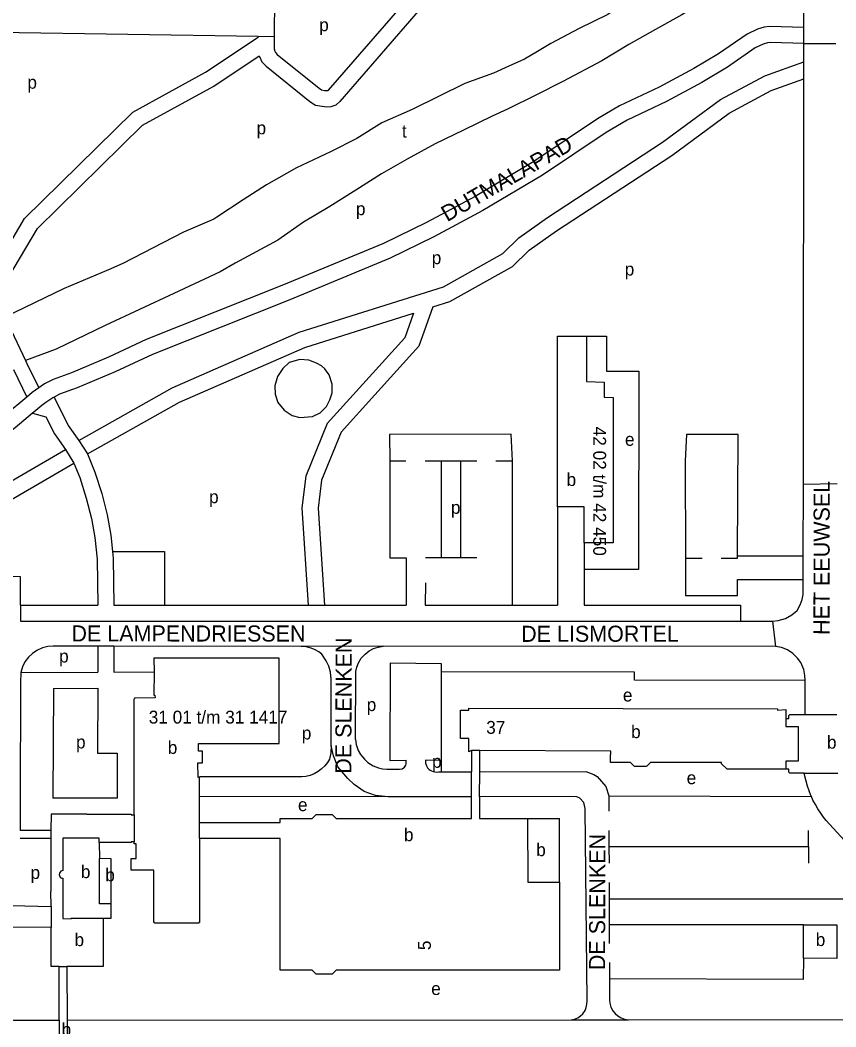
# Model space of a CAD drawing. Extents: x 161494 to 163033, y 383688 to 384862.
# Drawn here: x 161937.8 to 162191.5, y 384379.7 to 384692.8 of the extents above; entities that cross this region are included whole.
import ezdxf

# ---------------------------------------------------------------- set-up
doc = ezdxf.new("R2010")
doc.units = 0
for name, color, linetype in [('BLT_Basislijn', 7, 'Continuous'), ('BLT_Bebouwing', 7, 'Continuous'), ('BLT_Centroide', 7, 'Continuous'), ('BLT_Huisnummer', 7, 'Continuous'), ('BLT_Huisnummer_reeks', 7, 'Continuous'), ('BLT_Onderdoorgang_en_onderverdeling', 7, 'Continuous'), ('BLT_Onderverdeling_panden', 7, 'Continuous'), ('BLT_Straatnaam', 7, 'Continuous'), ('BLT_Vlakafsluiter', 7, 'Continuous')]:
    doc.layers.add(name, color=color, linetype=linetype)

msp = doc.modelspace()

# ---------------------------------------------------------------- linework, layer by layer
at = {"layer": 'BLT_Basislijn'}
for p, q in [((162016.89, 384703.11), (162016.86, 384687.59)), ((162181.54, 384685.47), (162181.58, 384690.47)), ((162011.86, 384687.67), (161924.77, 384689)), ((162016.86, 384687.59), (162011.86, 384687.67)), ((162011.86, 384687.67), (162011.86, 384687.48)), ((162181.54, 384679.83), (162181.54, 384685.47)), ((162181.53, 384674.52), (162181.54, 384679.83)), ((161933.32, 384599.9), (161939.51, 384586.93)), ((161939.51, 384586.93), (161939.95, 384586.02)), ((161935.8, 384584.12), (161939.88, 384575.55)), ((161939.95, 384586.02), (161943.64, 384578.39)), ((161939.6, 384576.15), (161939.92, 384575.48)), ((161956.03, 384562.03), (161958.78, 384557.84)), ((162160.93, 384526.09), (162161.16, 384563.86)), ((161951.91, 384559.21), (161954.55, 384554.96)), ((162052.76, 384555.73), (162057.83, 384555.71)), ((162063.83, 384555.71), (162068.84, 384555.71)), ((162068.84, 384555.71), (162074.81, 384555.73)), ((162068.88, 384525.52), (162068.84, 384555.71)), ((162074.81, 384555.73), (162079.83, 384555.73)), ((162074.81, 384555.73), (162074.82, 384525.52)), ((162085.82, 384555.72), (162090.97, 384555.72)), ((162104.97, 384541.44), (162104.95, 384510.84)), ((162113.27, 384530.18), (162113.26, 384521.96)), ((162068.88, 384525.52), (162063.88, 384525.55)), ((162074.82, 384525.52), (162068.88, 384525.52)), ((162079.83, 384525.51), (162074.82, 384525.52)), ((162144.72, 384525.48), (162149.9, 384525.49)), ((162113.26, 384521.96), (162113.25, 384510.84)), ((161982.68, 384510.82), (162027.43, 384510.83)), ((162027.43, 384510.83), (162032.44, 384510.83)), ((162032.44, 384510.83), (162057.84, 384510.83)), ((161938.06, 384489.92), (161961.94, 384490)), ((161966.94, 384490.02), (161979.47, 384490.06)), ((162068.9, 384462.53), (162068.89, 384490.05)), ((161948.15, 384484.96), (161948, 384450.8)), ((161948.15, 384484.96), (161961.96, 384485)), ((162052.25, 384451.18), (161993.63, 384451.3)), ((162120.9, 384451.58), (162120.92, 384446.72)), ((162188.54, 384443.92), (162202.39, 384428.59)), ((162120.94, 384440.71), (162120.96, 384435.72)), ((162183.02, 384435.72), (162183.02, 384440.72)), ((162183.02, 384435.72), (162120.96, 384435.72)), ((162120.96, 384435.72), (162120.98, 384430.56)), ((162183.02, 384435.72), (162183.02, 384430.57)), ((162121, 384424.58), (162121.02, 384419.5)), ((162121.02, 384419.5), (162121.05, 384411.45)), ((162181.45, 384411.45), (162121.05, 384411.45)), ((162121.05, 384411.45), (162121.07, 384405.65)), ((162121.09, 384399.74), (162121.11, 384394.62)), ((161952.4, 384381.82), (162109.2, 384381.87)), ((162127.04, 384381.9), (162197.47, 384381.94))]:
    msp.add_line(p, q, dxfattribs=at)
for points in [[(162129.11, 384719.89), (162129.02, 384714.31), (162102.45, 384714.98), (162102.34, 384709.99), (162074.52, 384710.46), (162037.26, 384667.41)], [(162148.13, 384713.48), (162144.15, 384710.95), (162136.26, 384705.43), (162127.66, 384699.69), (162120.65, 384694.55), (162111.65, 384690.15), (162102.89, 384685.49)], [(162181.58, 384690.47), (162181.57, 384697.92), (162179.73, 384698.26), (162179.65, 384698.65), (162179.7, 384710.65)], [(162033.72, 384670.96), (162060.84, 384702.3), (162016.89, 384703.11)], [(162152.23, 384699.94), (162143.61, 384694.45), (162135.39, 384689.81), (162127.17, 384685.16), (162118.75, 384680.11), (162106.58, 384673.66)], [(162181.58, 384690.47), (162170.99, 384690.82), (162169.27, 384690.61), (162167.13, 384689.99), (162163.92, 384688.44), (162155.07, 384682.28), (162147.39, 384677.7), (162136.59, 384671.9), (162124.27, 384666.11), (162117.38, 384662.05), (162097.62, 384648.8), (162079.31, 384637.89), (162064.26, 384629.82), (162050.86, 384623.33), (162019.78, 384610.42), (161977.05, 384593.41), (161965.31, 384587.97), (161953.76, 384583.06), (161948.07, 384581), (161945.42, 384579.62), (161943.64, 384578.39)], [(161927.72, 384611.79), (161939.21, 384631.09), (161972.91, 384664.14), (161995.43, 384676.54), (162011.86, 384687.48)], [(162016.86, 384687.59), (162016.85, 384683.82), (162017.01, 384683.09), (162017.21, 384682.66), (162017.76, 384682.08), (162030.81, 384671.55), (162031.56, 384671.1), (162032.46, 384670.92), (162033.26, 384670.84), (162033.61, 384670.86), (162033.72, 384670.96)], [(162181.54, 384685.47), (162171.21, 384685.81), (162170.27, 384685.7), (162168.93, 384685.31), (162166.45, 384684.11), (162157.78, 384678.08), (162149.86, 384673.35), (162138.84, 384667.43), (162126.61, 384661.68), (162120.04, 384657.82), (162100.29, 384644.57), (162081.78, 384633.54), (162066.53, 384625.37), (162052.91, 384618.77), (162021.66, 384605.79), (161979.03, 384588.82), (161967.34, 384583.4), (161955.59, 384578.41), (161950.09, 384576.41), (161948.36, 384575.51)], [(162102.89, 384685.49), (162098.77, 384683.04), (162094.64, 384680.59), (162089.84, 384678.41), (162085.04, 384676.24), (162076.12, 384673.08), (162067.93, 384669.03), (162059.75, 384664.98)], [(161930.29, 384606.33), (161943.18, 384627.98), (161975.92, 384660.1), (161998.03, 384672.26), (162012.19, 384681.69)], [(162012.19, 384681.69), (162012.24, 384681.48), (162013.04, 384679.79), (162014.37, 384678.39), (162027.93, 384667.44), (162029.72, 384666.36), (162031.72, 384665.97), (162033.18, 384665.82), (162034.57, 384665.92), (162036.07, 384666.38), (162037.26, 384667.41)], [(161956.03, 384562.03), (161985.15, 384578.44), (162024.57, 384595.69), (162069.49, 384609.84), (162087.97, 384620.17), (162092.95, 384625.08), (162101.81, 384631.37), (162137.64, 384654.77), (162155.64, 384668.09), (162169.39, 384675.47), (162181.54, 384679.83)], [(162066.16, 384603.55), (162071.48, 384605.23), (162091, 384616.13), (162096.17, 384621.23), (162104.62, 384627.24), (162140.5, 384650.66), (162158.32, 384663.86), (162171.43, 384670.89), (162181.53, 384674.52)], [(162181.47, 384548.49), (162181.48, 384572.05), (162181.53, 384674.52)], [(162106.58, 384673.66), (162098.22, 384669.44), (162089.36, 384665.08), (162084.61, 384662.86), (162075.75, 384658.55), (162066.89, 384654.24), (162058.17, 384649.52)], [(162059.75, 384664.98), (162050.36, 384660.84), (162042.49, 384655.98), (162034.34, 384651.83), (162029.05, 384649.32), (162023.76, 384646.81), (162014.45, 384641.59), (162007.23, 384636.84)], [(162058.17, 384649.52), (162050.23, 384645.01), (162042.18, 384639.9), (162034.12, 384634.79), (162025.97, 384629.93), (162018, 384624.3), (162004.71, 384617.15)], [(162007.23, 384636.84), (161999.01, 384631.46), (161998.02, 384630.82), (161988.6, 384626.81), (161979.17, 384621.93), (161969.73, 384617.06), (161965.3, 384615.12)], [(161965.3, 384615.12), (161951.55, 384609.34), (161933.1, 384600.35)], [(162004.71, 384617.15), (162000, 384614.53), (161985.64, 384607.72), (161964.3, 384597.76)], [(162066.16, 384603.55), (162061.86, 384591.4), (162048.17, 384576.26), (162037.66, 384564.63), (162031.57, 384549.65), (162030.5, 384541), (162032.44, 384510.83)], [(161958.78, 384557.84), (161987.38, 384573.96), (162026.33, 384591), (162060.19, 384601.67)], [(162060.19, 384601.67), (162057.48, 384594.01), (162033.36, 384567.33), (162026.69, 384550.92), (162025.48, 384541.14), (162027.43, 384510.83)], [(161964.3, 384597.76), (161949.05, 384590.48), (161939.51, 384586.93)], [(162113.93, 384594.52), (162120.16, 384594.52), (162120.15, 384583.57), (162130.26, 384583.56), (162130.17, 384521.94), (162113.26, 384521.96)], [(161943.64, 384578.39), (161941.54, 384576.94), (161939.88, 384575.55)], [(161939.88, 384575.55), (161933.16, 384569.9), (161930.17, 384567.61), (161923.57, 384564.05), (161880.13, 384543.25), (161875.48, 384541.33), (161869.42, 384539.18), (161866.4, 384538.3), (161863.11, 384537.18), (161860.29, 384535.54), (161858.06, 384533.63), (161845.78, 384521.31), (161828.11, 384504.08), (161797.59, 384474.82), (161795.64, 384472.79)], [(161948.36, 384575.51), (161948, 384575.33), (161945.83, 384573.83)], [(161948.36, 384575.51), (161952.79, 384566.68), (161956.03, 384562.03)], [(161945.83, 384573.83), (161944.57, 384572.96), (161942.1, 384570.88)], [(161941.64, 384570.5), (161936.29, 384566.01), (161932.9, 384563.4), (161925.84, 384559.59), (161882.17, 384538.68)], [(161942.1, 384570.88), (161941.64, 384570.5)], [(161941.64, 384570.5), (161945.84, 384569.38), (161948.49, 384564.11), (161951.91, 384559.21)], [(162090.97, 384555.72), (162090.5, 384564.04), (162052.74, 384563.94), (162052.76, 384555.73)], [(162161.16, 384563.86), (162145.05, 384563.85), (162144.71, 384555.68)], [(161874.22, 384530.27), (161904.04, 384535.88), (161925.46, 384543.89), (161951.91, 384559.21)], [(161958.78, 384557.84), (161961.04, 384552.24), (161963.2, 384545.51), (161964.9, 384538.87), (161965.98, 384532.58), (161966.52, 384527.52)], [(162052.76, 384555.73), (162052.81, 384525.55), (162057.85, 384525.55), (162057.84, 384510.83)], [(162090.95, 384510.84), (162090.97, 384555.72)], [(162144.71, 384555.68), (162144.72, 384525.48)], [(161866.38, 384519.73), (161875.14, 384525.35), (161905.39, 384531.04), (161927.61, 384539.35), (161954.55, 384554.96)], [(161954.55, 384554.96), (161956.34, 384550.54), (161958.39, 384544.12), (161960, 384537.82), (161961.03, 384531.89), (161961.74, 384525.15), (161961.97, 384510.82)], [(162181.41, 384526.07), (162181.47, 384548.49)], [(161966.52, 384527.52), (161982.68, 384527.52), (161982.68, 384510.82)], [(161966.52, 384527.52), (161966.74, 384525.45), (161966.97, 384510.82)], [(162144.72, 384525.48), (162144.72, 384513.85), (162160.94, 384513.8), (162160.93, 384518.79), (162181.39, 384518.82)], [(162155.89, 384525.45), (162160.92, 384525.46), (162160.93, 384526.09)], [(162181.41, 384526.07), (162160.93, 384526.09)], [(161937.92, 384510.81), (161937.97, 384519.69), (161866.38, 384519.73)], [(162063.85, 384517.79), (162063.82, 384510.83), (162090.95, 384510.84)], [(162171.83, 384505.85), (162173.58, 384506.03), (162175.85, 384506.72), (162177.88, 384507.78), (162179.47, 384509.17), (162180.42, 384510.93), (162181.01, 384512.55), (162181.33, 384514.13), (162181.39, 384515.77), (162181.39, 384518.82)], [(161937.92, 384510.81), (161961.97, 384510.82)], [(161937.92, 384510.81), (161937.92, 384505.81), (162161.9, 384505.85)], [(161966.97, 384510.82), (161982.68, 384510.82)], [(162090.95, 384510.84), (162104.95, 384510.84)], [(162113.25, 384510.84), (162161.9, 384510.85), (162161.9, 384505.85)], [(162161.9, 384505.85), (162171.83, 384505.85)], [(161961.95, 384498.05), (161948.12, 384498.06), (161946.46, 384497.94), (161944.73, 384497.52), (161943.05, 384496.77), (161941.62, 384495.8), (161940.38, 384494.61), (161939.32, 384493.17), (161938.57, 384491.66), (161938.06, 384489.92)], [(161961.95, 384498.05), (161961.94, 384490)], [(161966.95, 384498.04), (161961.95, 384498.05)], [(161966.95, 384498.04), (161966.94, 384490.02)], [(162025.21, 384498), (161966.95, 384498.04)], [(162034.56, 384467.09), (162034.55, 384487.85), (162034.3, 384489.95), (162033.82, 384491.89), (162033.05, 384493.49), (162031.65, 384495.55), (162030.73, 384496.27), (162029.53, 384496.96), (162028.32, 384497.48), (162026.77, 384497.85), (162025.21, 384498)], [(162042.17, 384469.03), (162042.27, 384490.23), (162042.5, 384491.54), (162043.07, 384492.94), (162043.92, 384494.36), (162045.09, 384495.64), (162046.4, 384496.63), (162047.76, 384497.36), (162049.19, 384497.8), (162050.76, 384498.03)], [(162172.71, 384497.96), (162050.76, 384498.03)], [(162181.99, 384487.36), (162181.89, 384489.01), (162181.52, 384490.78), (162180.6, 384492.95), (162179.63, 384494.36), (162178.19, 384495.82), (162176.48, 384496.97), (162174.59, 384497.68), (162172.71, 384497.96)], [(162068.89, 384490.05), (162068.9, 384492.62), (162052.87, 384492.82), (162052.83, 384462.56), (162057.9, 384462.6)], [(161938.06, 384489.92), (161937.9, 384486.8), (161937.83, 384449.68), (161937.82, 384440.72)], [(162181.99, 384487.36), (162128.86, 384487.52), (162128.86, 384490.01), (162068.89, 384490.05)], [(162182.02, 384476.83), (162181.99, 384487.36)], [(161961.96, 384485), (161961.87, 384464.85), (161968.01, 384464.82), (161967.98, 384450.79)], [(162042.17, 384469.03), (162042.33, 384467.49), (162042.99, 384465.59), (162043.72, 384464.37), (162044.94, 384462.97), (162046, 384461.92), (162047.67, 384460.86), (162049.29, 384460.24), (162050.51, 384459.91), (162051.85, 384459.8), (162055.78, 384459.87), (162056.64, 384459.97), (162057.37, 384460.47), (162057.76, 384461.08), (162057.87, 384461.47), (162057.9, 384462.6)], [(162034.56, 384467.09), (162034.46, 384464.89), (162034, 384462.93), (162033.43, 384461.95), (162032.58, 384460.85), (162031.48, 384459.79), (162030.53, 384459.08), (162029.32, 384458.41), (162027.98, 384457.89), (162026.72, 384457.6), (162025.42, 384457.46), (161993.61, 384457.42), (161993.61, 384457.28)], [(162052.25, 384451.18), (162048.39, 384451.62), (162044.81, 384452.92), (162041.71, 384455.07), (162039.77, 384456.89), (162036.66, 384460.51), (162035.27, 384463.98), (162034.56, 384467.09)], [(162068.9, 384462.53), (162063.88, 384462.68), (162063.87, 384462.16), (162063.93, 384461.65), (162064.07, 384461.15), (162064.29, 384460.67), (162064.57, 384460.24), (162064.92, 384459.85), (162065.33, 384459.53), (162065.77, 384459.27), (162066.26, 384459.08), (162066.77, 384458.96), (162067.29, 384458.93), (162067.89, 384458.99), (162068.89, 384458.99)], [(162068.89, 384458.99), (162068.9, 384462.53)], [(162068.89, 384458.99), (162075.36, 384458.99), (162078.23, 384458.99)], [(162080.8, 384459), (162113.74, 384459.1), (162116.28, 384458.22), (162117.33, 384457.52), (162119.94, 384454.41), (162120.9, 384451.58)], [(162183.93, 384451.29), (162183.77, 384451.64), (162183.19, 384453.09), (162182.69, 384454.58), (162182.26, 384456.08), (162181.91, 384457.61), (162181.72, 384458.64)], [(161967.98, 384450.79), (161948, 384450.8)], [(162078.21, 384451.24), (162052.25, 384451.18)], [(162109.2, 384381.87), (162110.19, 384382.06), (162111.25, 384382.49), (162112.13, 384383.08), (162112.87, 384383.8), (162113.53, 384384.78), (162113.92, 384385.74), (162114.11, 384386.72), (162114.13, 384387.77), (162113.58, 384447.65), (162113.1, 384449.48), (162111.88, 384450.77), (162110.95, 384451.23), (162108.81, 384451.31), (162080.74, 384451.24)], [(162120.9, 384451.58), (162183.93, 384451.29)], [(162188.54, 384443.92), (162187.73, 384444.91), (162186.81, 384446.17), (162185.94, 384447.48), (162185.15, 384448.83), (162184.42, 384450.21), (162183.93, 384451.29)], [(162121.02, 384419.5), (162202.39, 384419.51), (162202.39, 384428.59)], [(161935.11, 384421.74), (161935.13, 384417.47), (161947.42, 384417.17)], [(161947.42, 384410.59), (161930.9, 384410.67), (161930.25, 384410.65), (161929.61, 384410.55), (161928.98, 384410.38), (161928.39, 384410.13), (161927.82, 384409.8), (161927.31, 384409.42), (161926.84, 384408.96), (161926.43, 384408.46), (161926.09, 384407.54), (161925.87, 384406.59), (161925.89, 384404.18), (161925.93, 384392.05), (161926.1, 384390.22), (161926.44, 384388.78), (161926.86, 384387.75), (161927.3, 384386.88), (161928.5, 384385.23), (161930.12, 384383.71), (161932, 384382.63), (161933.72, 384382.03), (161935.75, 384381.78), (161950, 384381.82)], [(162181.42, 384401.02), (162181.4, 384394.44), (162121.11, 384394.62)], [(162121.11, 384394.62), (162121.13, 384388.1), (162121.23, 384387.06), (162121.59, 384385.81), (162122.16, 384384.71), (162122.86, 384383.83), (162123.69, 384383.1), (162124.78, 384382.46), (162125.82, 384382.09), (162127.04, 384381.9)]]:
    msp.add_lwpolyline(points, dxfattribs=at)
msp.add_lwpolyline([(162030.01, 384586.11), (162027.62, 384587.06), (162024.81, 384587.19), (162021.53, 384586.24), (162019.55, 384584.42), (162017.88, 384581.98), (162017.08, 384579.01), (162017.09, 384576.43), (162018.02, 384573.83), (162019.95, 384571.42), (162022.45, 384569.82), (162024.85, 384569.21), (162028.7, 384569.45), (162031.1, 384570.67), (162033.13, 384572.65), (162034.12, 384574.72), (162034.82, 384576.9), (162034.85, 384579.59), (162033.91, 384582.5), (162032.6, 384584.28), (162031.5, 384585.29)], close=True, dxfattribs=at)
at = {"layer": 'BLT_Bebouwing'}
for p, q in [((162018.4, 384467.78), (162018.41, 384494.35)), ((162182.42, 384476.83), (162191.79, 384476.84)), ((162078.21, 384451.24), (162078.23, 384458.99)), ((162080.74, 384451.24), (162080.8, 384459)), ((162181.72, 384458.64), (162192.18, 384458.64)), ((162095.63, 384444.49), (162105.57, 384444.5)), ((162105.57, 384424.67), (162105.57, 384444.5)), ((161947.42, 384417.17), (161947.42, 384410.59)), ((162181.42, 384401.02), (162181.45, 384411.45)), ((161950, 384381.82), (161950, 384370.98)), ((161952.4, 384381.82), (161952.43, 384370.98))]:
    msp.add_line(p, q, dxfattribs=at)
for points in [[(162104.97, 384541.44), (162104.96, 384594.52), (162113.93, 384594.52)], [(162113.93, 384594.52), (162113.93, 384580.39), (162119.42, 384580.21), (162119.42, 384575.48), (162122.22, 384575.45), (162122.24, 384530.21), (162113.27, 384530.18)], [(162113.27, 384530.18), (162113.27, 384541.41), (162104.97, 384541.44)], [(162018.41, 384494.35), (161979.43, 384494.38), (161979.47, 384490.06)], [(161979.47, 384490.06), (161979.45, 384482.86), (161979.76, 384482.85), (161979.79, 384481.98), (161973.43, 384481.93), (161973.43, 384481.75), (161973.25, 384481.75)], [(161973.28, 384445.61), (161973.25, 384481.75)], [(162078.25, 384465.64), (162077.34, 384465.27), (162077.34, 384469.33), (162074.76, 384469.33), (162074.77, 384478.18)], [(162074.77, 384478.18), (162077.34, 384478.18), (162077.34, 384478.78), (162173.43, 384478.63), (162173.43, 384478.22), (162175.96, 384478.37), (162175.96, 384475.59)], [(162175.96, 384475.59), (162176.93, 384475.59), (162176.93, 384476.52), (162177.24, 384476.83), (162182.02, 384476.83)], [(162182.02, 384476.83), (162182.42, 384476.83)], [(161993.61, 384457.28), (161993.14, 384457.26), (161993.13, 384461.83), (161994.55, 384461.83), (161994.55, 384465.45), (161993.34, 384465.45), (161993.3, 384467.77), (162018.4, 384467.78)], [(162078.25, 384465.64), (162078.23, 384458.99)], [(162080.8, 384459), (162080.78, 384465.62)], [(162175.98, 384459.86), (162157.7, 384459.88), (162157.58, 384459.93), (162156.01, 384461.48), (162155.96, 384461.61), (162155.96, 384461.88), (162133.84, 384461.88), (162132.69, 384460.73), (162132.56, 384460.67), (162128.9, 384460.68), (162128.77, 384460.73), (162127.63, 384461.88), (162121.47, 384461.86), (162121.46, 384464.37), (162121.59, 384464.37), (162121.59, 384465.41), (162080.78, 384465.62)], [(162176.89, 384459.86), (162175.98, 384459.86)], [(162181.72, 384458.64), (162177.21, 384458.64), (162176.91, 384458.93), (162176.89, 384459.86)], [(161993.63, 384451.3), (161993.61, 384457.28)], [(161993.64, 384443.25), (161993.63, 384451.3)], [(162018.71, 384443.27), (162018.71, 384444.5), (162028.65, 384444.51), (162029.9, 384445.75), (162034.84, 384445.78), (162036.1, 384444.51), (162078.19, 384444.48), (162078.21, 384451.24)], [(162080.74, 384451.24), (162080.71, 384444.48)], [(161958.58, 384445.79), (161947.43, 384445.8), (161947.41, 384440.73)], [(161958.58, 384445.79), (161972.36, 384445.79), (161972.36, 384445.61), (161973.28, 384445.61)], [(161993.64, 384443.25), (162018.71, 384443.27)], [(162080.71, 384444.48), (162095.63, 384444.49)], [(161947.41, 384440.73), (161937.82, 384440.72)], [(161937.81, 384438.33), (161947.41, 384438.33)], [(161947.41, 384438.33), (161947.41, 384421.82)], [(161962.45, 384437.01), (161962.45, 384438.35)], [(161973.28, 384437.19), (161972.36, 384437.19), (161972.36, 384437.01), (161962.45, 384437.01)], [(161962.45, 384437.01), (161962.48, 384432.02)], [(161993.64, 384438.31), (161993.63, 384412.15), (161993.43, 384412.15), (161993.44, 384411.96), (161979.65, 384411.95), (161979.65, 384412.15), (161979.45, 384412.15), (161979.43, 384428.46), (161972.33, 384428.45), (161972.34, 384432.08), (161973.89, 384432.08), (161973.88, 384436.66), (161973.28, 384436.66), (161973.28, 384437.19)], [(162018.72, 384438.28), (161993.64, 384438.31)], [(162105.58, 384397.33), (162036.11, 384397.35), (162034.89, 384396.13), (162029.91, 384396.09), (162028.66, 384397.34), (162018.73, 384397.35), (162018.72, 384438.28)], [(161966.09, 384417.93), (161966.11, 384432), (161962.48, 384432.02)], [(162105.57, 384424.67), (162105.58, 384397.33)], [(161947.42, 384417.17), (161947.41, 384421.82)], [(161963.69, 384413.52), (161966.08, 384413.51), (161966.09, 384417.93)], [(161963.69, 384413.52), (161963.65, 384398.52), (161952.38, 384398.52)], [(162181.45, 384411.45), (162191.85, 384411.43), (162191.82, 384401), (162181.42, 384401.02)], [(161947.42, 384398.52), (161947.42, 384410.59)], [(161949.98, 384398.52), (161947.42, 384398.52)], [(161950, 384381.82), (161949.98, 384398.52)], [(161952.38, 384398.52), (161952.4, 384381.82)]]:
    msp.add_lwpolyline(points, dxfattribs=at)
at = {"layer": 'BLT_Onderdoorgang_en_onderverdeling'}
msp.add_line((162080.78, 384465.62), (162078.25, 384465.64), dxfattribs=at)
for points in [[(162175.96, 384475.59), (162175.97, 384473.14), (162179.77, 384473.14), (162179.76, 384462.36), (162175.96, 384462.34), (162175.98, 384459.86)], [(162095.63, 384444.49), (162095.68, 384424.67), (162105.57, 384424.67)]]:
    msp.add_lwpolyline(points, dxfattribs=at)
at = {"layer": 'BLT_Onderverdeling_panden'}
for p, q in [((161973.28, 384445.61), (161973.28, 384437.19)), ((161993.64, 384438.31), (161993.64, 384443.25)), ((161947.41, 384440.73), (161947.41, 384438.33)), ((161949.98, 384398.52), (161952.38, 384398.52))]:
    msp.add_line(p, q, dxfattribs=at)
for points in [[(161962.45, 384438.35), (161951.12, 384438.36), (161951.14, 384428.27), (161950.8, 384428.22), (161950.51, 384428.07), (161950.24, 384427.83), (161950.04, 384427.46), (161949.98, 384427.08), (161950.02, 384426.81), (161950.13, 384426.48), (161950.3, 384426.25), (161950.53, 384426.08), (161950.76, 384425.95), (161951.13, 384425.89), (161951.13, 384413.35), (161953.69, 384413.34), (161953.69, 384413.53), (161963.69, 384413.52)], [(161966.09, 384417.93), (161962.5, 384417.94), (161962.48, 384432.02)]]:
    msp.add_lwpolyline(points, dxfattribs=at)
at = {"layer": 'BLT_Vlakafsluiter'}
for p, q in [((162181.54, 384685.47), (162191.56, 384685.46)), ((162181.47, 384548.49), (162191.97, 384548.7)), ((162171.83, 384505.85), (162172.71, 384497.96)), ((162050.76, 384498.03), (162025.21, 384498)), ((162109.2, 384381.87), (162127.04, 384381.9))]:
    msp.add_line(p, q, dxfattribs=at)
msp.add_lwpolyline([(162181.39, 384518.82), (162181.41, 384526.07)], dxfattribs=at)

# ---------------------------------------------------------------- texts
at = {"layer": 'BLT_Centroide'}
for s, p in [('p', (162030.83, 384689.31)), ('p', (161940.07, 384671.43)), ('p', (162011.36, 384657.25)), ('t', (162056.56, 384656.26)), ('p', (162042.26, 384632.1)), ('p', (162065.84, 384616.87)), ('p', (162125.86, 384613.33)), ('e', (162125.94, 384560.39)), ('b', (162107.77, 384547.89)), ('p', (161996.58, 384542.54)), ('p', (162071.81, 384539.22)), ('p', (161949.94, 384493)), ('e', (162125.29, 384480.88)), ('p', (162045.61, 384477.9)), ('p', (162025.43, 384469.07)), ('b', (162127.84, 384469.48)), ('p', (161955.2, 384466.28)), ('b', (161983.73, 384464.58)), ('b', (162188.76, 384466.21)), ('p', (162065.93, 384460.26)), ('e', (162145.14, 384455.15)), ('e', (162024.24, 384446.79)), ('b', (162057.19, 384437.44)), ('b', (162098.33, 384432.78)), ('b', (161956.7, 384425.94)), ('p', (161941.05, 384425.69)), ('b', (161964.3, 384424.97)), ('b', (161954.73, 384404.8)), ('b', (162185.27, 384404.83)), ('e', (162065.68, 384389.61)), ('b', (161950.71, 384376.9))]:
    msp.add_text(s, height=4, dxfattribs=at).set_placement(p)
at = {"layer": 'BLT_Huisnummer'}
for s, rotation, p in [('37', 359.77, (162082.77, 384470.83)), ('5', 89.838, (162065.57, 384403.55))]:
    msp.add_text(s, height=4, rotation=rotation, dxfattribs=at).set_placement(p)
at = {"layer": 'BLT_Huisnummer_reeks'}
msp.add_text('42 02 t/m 42 450', height=4, rotation=270, dxfattribs=at).set_placement((162116.07, 384566.32))
msp.add_text('31 01 t/m 31 1417', height=4, dxfattribs=at).set_placement((161977.82, 384474.02))
at = {"layer": 'BLT_Straatnaam'}
for s, height, rotation, p in [('DUTMALAPAD', 5, 30, (162070.63, 384629.9)), ('HET EEUWSEL', 4.9999, 89.9239, (162189.56, 384501.57)), ('DE LAMPENDRIESSEN', 5, 359.9848, (161953.77, 384499.54)), ('DE LISMORTEL', 5, 0.0477, (162093.64, 384499.42)), ('DE SLENKEN', 5, 89.8583, (162040.84, 384458.4)), ('DE SLENKEN', 5, 89.8583, (162119.75, 384397.32))]:
    msp.add_text(s, height=height, rotation=rotation, dxfattribs=at).set_placement(p)

doc.saveas('drawing.dxf')
